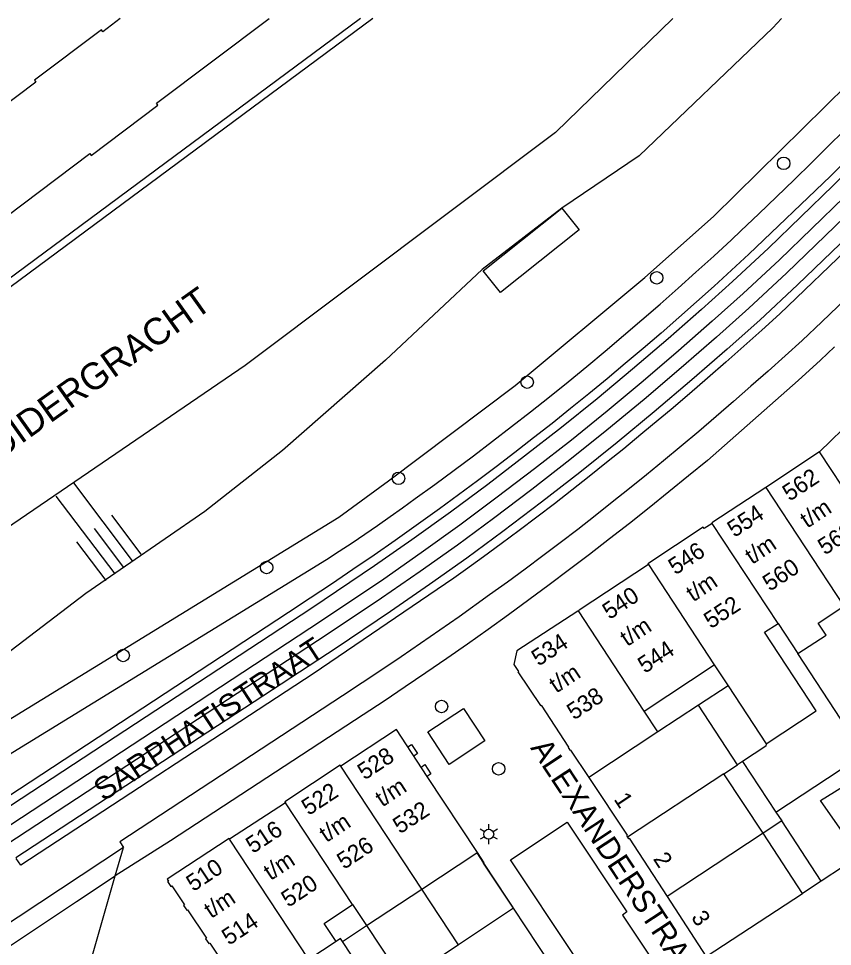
# Model space of a CAD drawing. Extents: x 122462 to 123306, y 485548 to 486417.
# Drawn here: x 123158.7 to 123231.7, y 486333.7 to 486417 of the extents above; entities that cross this region are included whole.
import ezdxf

# ---------------------------------------------------------------- set-up
doc = ezdxf.new("R2010")
doc.units = 0
for name, color, linetype in [('Level 1', 7, 'Continuous'), ('Level 16', 7, 'Continuous'), ('Level 17', 7, 'Continuous'), ('Level 19', 7, 'Continuous'), ('Level 20', 7, 'Continuous'), ('Level 22', 7, 'Continuous'), ('Level 24', 7, 'Continuous'), ('Level 37', 7, 'Continuous'), ('Level 4', 7, 'Continuous'), ('Level 40', 7, 'Continuous'), ('Level 48', 7, 'Continuous'), ('Level 50', 7, 'Continuous'), ('Level 53', 7, 'Continuous'), ('Level 57', 7, 'Continuous'), ('Level 58', 7, 'Continuous'), ('Level 59', 7, 'Continuous'), ('Level 60', 7, 'Continuous')]:
    doc.layers.add(name, color=color, linetype=linetype)

msp = doc.modelspace()

# ---------------------------------------------------------------- linework, layer by layer
at = {"layer": 'Level 1'}
for p, q in [((123235.039, 486382.526), (123230.529, 486378.09)), ((123230.529, 486378.09), (123225.704, 486374.909)), ((123226.804, 486362.716), (123228.584, 486360.007)), ((123214.811, 486354.86), (123221.09, 486358.986)), ((123221.09, 486358.986), (123222.318, 486357.117)), ((123222.318, 486357.117), (123225.737, 486351.915)), ((123219.662, 486355.372), (123216.038, 486352.992)), ((123223.171, 486350.032), (123219.662, 486355.372)), ((123216.038, 486352.992), (123214.811, 486354.86)), ((123221.95, 486349.23), (123223.171, 486350.032)), ((123199.84, 486342.17), (123195.333, 486349.001)), ((123225.459, 486343.89), (123221.95, 486349.23)), ((123182.621, 486346.637), (123177.614, 486343.359)), ((123228.995, 486338.508), (123225.459, 486343.89)), ((123194.85, 486338.882), (123199.786, 486342.135)), ((123199.786, 486342.135), (123199.84, 486342.17)), ((123232.673, 486340.925), (123230.678, 486339.614)), ((123230.678, 486339.614), (123228.995, 486338.508)), ((123189.886, 486335.611), (123194.85, 486338.882)), ((123188.645, 486337.494), (123189.886, 486335.611)), ((123191.074, 486329.173), (123187.728, 486334.188))]:
    msp.add_line(p, q, dxfattribs=at)
for points in [[(123167.795, 486416.958), (123166.225, 486415.776), (123166.105, 486415.936), (123160.112, 486411.424), (123160.232, 486411.265), (123148.252, 486402.244), (123148.132, 486402.404), (123143.918, 486399.231), (123148.989, 486392.497), (123153.203, 486395.67), (123153.083, 486395.83), (123165.062, 486404.849), (123165.182, 486404.69), (123171.175, 486409.202), (123171.055, 486409.362), (123181.145, 486416.958)], [(123225.704, 486374.909), (123220.88, 486371.729), (123220.909, 486371.686)], [(123220.909, 486371.686), (123220.173, 486371.225), (123220.09, 486371.35), (123215.12, 486368.069), (123215.176, 486367.987)], [(123215.176, 486367.987), (123208.959, 486363.9), (123208.9, 486363.855)], [(123208.9, 486363.855), (123208.84, 486363.809), (123203.38, 486360.249), (123203.1, 486359.029), (123203.528, 486358.392), (123203.479, 486358.36), (123205.499, 486355.35), (123205.551, 486355.384), (123208.021, 486351.614), (123207.969, 486351.579), (123208.15, 486351.309), (123208.198, 486351.342), (123209.819, 486348.906)], [(123228.584, 486360.007), (123231.114, 486361.67), (123230.403, 486362.751), (123232.701, 486364.262)], [(123225.737, 486351.915), (123230.237, 486354.872), (123225.602, 486361.926), (123226.804, 486362.716)], [(123195.333, 486349.001), (123192.57, 486353.189), (123187.585, 486349.906)], [(123187.585, 486349.906), (123187.529, 486349.989), (123182.559, 486346.729), (123182.621, 486346.637)], [(123240.501, 486343.552), (123243.294, 486339.302), (123238.114, 486336.108), (123230.623, 486346.845), (123236.113, 486350.23)], [(123209.819, 486348.906), (123213.265, 486343.727), (123213.209, 486343.689), (123213.305, 486343.55)], [(123177.614, 486343.359), (123177.559, 486343.439), (123172.019, 486339.769), (123172.126, 486339.611), (123172.049, 486339.559), (123172.342, 486339.12), (123172.426, 486339.176), (123173.557, 486337.472), (123173.473, 486337.416), (123173.758, 486336.987), (123173.842, 486337.043), (123175.539, 486334.486), (123175.455, 486334.43), (123175.739, 486333.999), (123175.821, 486334.054), (123179.246, 486328.91)], [(123213.305, 486343.55), (123213.4, 486343.41), (123213.457, 486343.447), (123216.848, 486338.233)], [(123216.848, 486338.233), (123220.33, 486332.88), (123220.37, 486332.839)], [(123187.163, 486334.191), (123186.094, 486335.813), (123188.645, 486337.494)], [(123187.728, 486334.188), (123187.553, 486334.451), (123187.163, 486334.191)]]:
    msp.add_lwpolyline(points, dxfattribs=at)
at = {"layer": 'Level 16'}
for points in [[(123190.452, 486416.958), (123152.084, 486388.57), (123141.474, 486380.8), (123112.044, 486361.399), (123104.38, 486356.401), (123085.904, 486344.353)], [(123217.361, 486416.958), (123206.829, 486406.748), (123179.003, 486385.844), (123152.655, 486367.889), (123137.927, 486357.79), (123128.826, 486350.852), (123125.877, 486348.714), (123125.807, 486348.517), (123125.744, 486347.678)]]:
    msp.add_lwpolyline(points, dxfattribs=at)
at = {"layer": 'Level 17'}
for p, q in [((123168.085, 486342.615), (123154.252, 486333.498)), ((123167.35, 486340.065), (123168.085, 486342.615)), ((123203.068, 486337.175), (123200.395, 486341.211)), ((123206.397, 486332.15), (123203.068, 486337.175))]:
    msp.add_line(p, q, dxfattribs=at)
for points in [[(123132.782, 486338.745), (123187.402, 486372.258), (123191.877, 486375.508), (123203.236, 486384.06), (123214.862, 486393.723), (123221.004, 486399.216), (123239.035, 486416.958)], [(123134.337, 486336.539), (123186.289, 486368.432), (123187.449, 486369.18), (123188.601, 486369.939), (123189.745, 486370.711), (123190.881, 486371.494), (123192.009, 486372.289), (123193.129, 486373.095), (123194.266, 486373.908), (123196.013, 486375.173), (123197.751, 486376.452), (123199.479, 486377.743), (123201.198, 486379.046), (123202.907, 486380.363), (123204.607, 486381.692), (123206.296, 486383.034), (123207.975, 486384.388), (123209.645, 486385.754), (123211.304, 486387.133), (123212.953, 486388.524), (123214.592, 486389.927), (123216.22, 486391.342), (123217.838, 486392.769), (123219.445, 486394.208), (123221.041, 486395.659), (123222.627, 486397.122), (123223.475, 486397.918), (123225.077, 486399.435), (123226.669, 486400.962), (123228.254, 486402.497), (123229.829, 486404.042), (123242.851, 486416.958)], [(123240.448, 486411.733), (123231.513, 486402.822), (123224.18, 486395.824), (123222.627, 486394.388), (123221.063, 486392.963), (123219.489, 486391.549), (123217.905, 486390.146), (123216.311, 486388.756), (123214.707, 486387.376), (123213.093, 486386.009), (123211.469, 486384.653), (123209.835, 486383.309), (123208.191, 486381.977), (123206.538, 486380.657), (123204.876, 486379.348), (123203.204, 486378.052), (123201.522, 486376.768), (123199.832, 486375.497), (123198.132, 486374.237), (123196.423, 486372.99), (123194.346, 486371.486), (123192.458, 486370.159), (123190.563, 486368.844), (123188.659, 486367.541), (123186.748, 486366.249), (123184.828, 486364.969), (123182.901, 486363.701), (123155.674, 486345.856)], [(123233.643, 486396.861), (123226.958, 486390.473), (123225.355, 486389.02), (123223.742, 486387.577), (123222.121, 486386.144), (123220.492, 486384.721), (123218.853, 486383.308), (123217.206, 486381.905), (123215.551, 486380.512), (123214.513, 486379.647), (123212.976, 486378.386), (123211.431, 486377.136), (123209.877, 486375.897), (123208.315, 486374.668), (123206.745, 486373.449), (123205.166, 486372.242), (123203.579, 486371.045), (123201.984, 486369.859), (123200.381, 486368.684), (123198.77, 486367.52), (123197.718, 486366.769), (123185.114, 486358.179), (123158.867, 486341.039), (123158.471, 486341.637)], [(123235.817, 486394.627), (123230.74, 486389.75), (123228.981, 486388.1), (123227.453, 486386.717), (123225.917, 486385.343), (123224.372, 486383.978), (123222.82, 486382.622), (123221.259, 486381.277), (123219.689, 486379.94), (123218.112, 486378.613), (123216.527, 486377.296), (123215.005, 486376.046), (123213.475, 486374.805), (123211.936, 486373.576), (123210.389, 486372.357), (123208.834, 486371.149), (123207.27, 486369.951), (123205.699, 486368.764), (123204.119, 486367.588), (123202.531, 486366.422), (123200.935, 486365.268), (123198.192, 486363.314), (123196.469, 486362.103), (123194.739, 486360.904), (123193, 486359.717), (123191.253, 486358.541), (123189.498, 486357.377), (123187.736, 486356.225), (123167.755, 486343.119), (123168.085, 486342.615)], [(123231.88, 486387.504), (123230.608, 486386.337), (123228.6, 486384.512), (123226.582, 486382.7), (123224.554, 486380.899), (123222.515, 486379.109), (123220.465, 486377.332), (123218.773, 486375.936), (123217.017, 486374.506), (123215.251, 486373.089), (123213.476, 486371.682), (123211.692, 486370.288), (123209.898, 486368.906), (123208.095, 486367.536), (123206.283, 486366.178), (123204.462, 486364.832), (123202.632, 486363.498), (123200.793, 486362.177), (123198.945, 486360.867), (123197.089, 486359.571), (123195.224, 486358.286), (123193.35, 486357.014), (123191.468, 486355.755), (123189.578, 486354.508), (123172.296, 486343.228), (123167.35, 486340.065)], [(123197.317, 486350.064), (123195.386, 486352.984), (123198.577, 486355.093), (123200.507, 486352.174), (123197.317, 486350.064)], [(123211.501, 486327.09), (123207.817, 486332.615), (123208.445, 486333.027), (123202.793, 486341.511), (123207.898, 486344.898), (123213.254, 486336.835), (123212.846, 486336.553), (123216.803, 486330.632), (123211.501, 486327.09)], [(123200.395, 486341.211), (123200.454, 486341.25), (123199.84, 486342.17)], [(123155.775, 486332.404), (123163.868, 486337.789), (123167.35, 486340.065)], [(123165.676, 486332.334), (123165.243, 486332.75), (123167.35, 486340.065)]]:
    msp.add_lwpolyline(points, dxfattribs=at)
at = {"layer": 'Level 19'}
for p, q in [((123189.359, 486416.958), (123151.706, 486389.073)), ((123233.016, 486353.261), (123228.584, 486360.007)), ((123222.318, 486357.117), (123219.662, 486355.372)), ((123223.633, 486350.335), (123223.171, 486350.032)), ((123223.633, 486350.335), (123226.616, 486345.796)), ((123226.616, 486345.796), (123234.512, 486350.984)), ((123226.616, 486345.796), (123227.142, 486344.996)), ((123227.142, 486344.996), (123225.459, 486343.89)), ((123230.678, 486339.614), (123227.142, 486344.996)), ((123198.141, 486333.888), (123194.85, 486338.882)), ((123203.068, 486337.175), (123198.141, 486333.888)), ((123187.728, 486334.188), (123189.886, 486335.611)), ((123189.886, 486335.611), (123193.225, 486330.608)), ((123198.141, 486333.888), (123194.336, 486331.35))]:
    msp.add_line(p, q, dxfattribs=at)
msp.add_lwpolyline([(123225.737, 486351.915), (123225.721, 486351.708), (123223.633, 486350.335)], dxfattribs=at)
at = {"layer": 'Level 20'}
msp.add_lwpolyline([(123227.128, 486416.958), (123226.347, 486416.118), (123214.358, 486404.642), (123207.4, 486399.966), (123200.277, 486394.449), (123191.597, 486386.324), (123182.341, 486378.222), (123175.379, 486372.758), (123164.712, 486365.388), (123158.016, 486360.276), (123153.237, 486354.953), (123145.688, 486350.946), (123140.068, 486347.272), (123131.328, 486340.807)], dxfattribs=at)
at = {"layer": 'Level 22'}
msp.add_line((123200.395, 486341.211), (123203.538, 486336.466), dxfattribs=at)
at = {"layer": 'Level 24'}
msp.add_line((123199.786, 486342.135), (123200.395, 486341.211), dxfattribs=at)
at = {"layer": 'Level 37'}
for points in [[(123241.03, 486411.185), (123231.744, 486401.974), (123225.952, 486396.381), (123222.721, 486393.366), (123219.946, 486390.881), (123216.94, 486388.248), (123213.765, 486385.527), (123210.569, 486382.869), (123207.368, 486380.288), (123204.076, 486377.707), (123200.759, 486375.175), (123197.416, 486372.695), (123193.966, 486370.217), (123190.616, 486367.88), (123184.983, 486364.082), (123156.102, 486345.165)], [(123242.034, 486410.153), (123232.751, 486400.945), (123226.939, 486395.332), (123223.692, 486392.302), (123220.904, 486389.806), (123217.883, 486387.161), (123214.693, 486384.426), (123211.482, 486381.755), (123208.265, 486379.161), (123204.957, 486376.568), (123201.624, 486374.024), (123198.265, 486371.533), (123194.8, 486369.043), (123191.437, 486366.696), (123185.777, 486362.88), (123156.905, 486343.969)], [(123242.948, 486409.215), (123233.663, 486400.005), (123227.574, 486394.133), (123224.193, 486390.984), (123221.287, 486388.391), (123218.124, 486385.639), (123214.783, 486382.796), (123211.462, 486380.052), (123208.135, 486377.388), (123204.717, 486374.728), (123201.271, 486372.12), (123198.042, 486369.744), (123194.714, 486367.37), (123191.238, 486364.965), (123186.373, 486361.706), (123157.637, 486342.879)], [(123243.952, 486408.183), (123234.67, 486398.976), (123228.56, 486393.083), (123225.163, 486389.918), (123222.242, 486387.313), (123219.064, 486384.548), (123215.707, 486381.691), (123212.37, 486378.935), (123209.028, 486376.258), (123205.594, 486373.586), (123202.132, 486370.966), (123198.888, 486368.578), (123195.543, 486366.192), (123192.054, 486363.778), (123187.166, 486360.503), (123158.44, 486341.683)]]:
    msp.add_lwpolyline(points, dxfattribs=at)
at = {"layer": 'Level 4'}
for p, q in [((123237.525, 486367.443), (123230.529, 486378.09)), ((123225.704, 486374.909), (123232.701, 486364.262)), ((123226.804, 486362.716), (123220.909, 486371.686)), ((123215.176, 486367.987), (123221.09, 486358.986)), ((123214.811, 486354.86), (123208.9, 486363.855)), ((123216.038, 486352.992), (123209.819, 486348.906)), ((123194.85, 486338.882), (123187.585, 486349.906)), ((123221.95, 486349.23), (123213.305, 486343.55)), ((123188.645, 486337.494), (123182.621, 486346.637)), ((123225.459, 486343.89), (123216.848, 486338.233)), ((123184.726, 486332.565), (123177.614, 486343.359)), ((123220.37, 486332.839), (123228.995, 486338.508)), ((123187.163, 486334.191), (123184.726, 486332.565))]:
    msp.add_line(p, q, dxfattribs=at)
at = {"layer": 'Level 40'}
for points in [[(123193.585, 486351.652), (123193.918, 486351.871), (123194.468, 486351.037), (123194.135, 486350.818)], [(123194.783, 486349.835), (123195.117, 486350.055), (123195.667, 486349.221), (123195.333, 486349.001)]]:
    msp.add_lwpolyline(points, dxfattribs=at)
at = {"layer": 'Level 48'}
msp.add_lwpolyline([(123201.906, 486392.386), (123200.346, 486394.343), (123207.4, 486399.966), (123208.96, 486398.009), (123201.906, 486392.386)], dxfattribs=at)
at = {"layer": 'Level 50'}
for p, q in [((123200.851, 486344.257), (123200.851, 486344.707)), ((123200.461, 486344.032), (123200.071, 486344.257)), ((123201.63, 486344.257), (123201.24, 486344.032)), ((123200.461, 486343.582), (123200.071, 486343.357)), ((123200.851, 486342.907), (123200.851, 486343.357)), ((123201.63, 486343.357), (123201.24, 486343.582))]:
    msp.add_line(p, q, dxfattribs=at)
msp.add_circle((123200.851, 486343.807), 0.45, dxfattribs=at)
at = {"layer": 'Level 53'}
for centre in [(123227.312, 486403.968), (123215.922, 486393.711), (123204.296, 486384.35), (123192.764, 486375.72), (123180.926, 486367.729), (123168.056, 486359.834), (123196.624, 486355.261), (123201.743, 486349.671)]:
    msp.add_circle(centre, 0.56, dxfattribs=at)
at = {"layer": 'Level 57'}
for p, q in [((123168.902, 486368.337), (123163.634, 486375.313)), ((123167.328, 486367.148), (123162.06, 486374.124)), ((123169.689, 486368.931), (123167.055, 486372.419)), ((123168.115, 486367.743), (123165.481, 486371.231)), ((123166.542, 486366.554), (123163.907, 486370.042))]:
    msp.add_line(p, q, dxfattribs=at)

# ---------------------------------------------------------------- texts
at = {"layer": 'Level 58'}
for s, rotation, p in [('562', 33.30586, (123227.835, 486373.625)), ('554', 33.30586, (123222.888, 486370.376)), ('t/m', 33.30586, (123229.42, 486371.21)), ('568', 33.30586, (123231.009, 486368.794)), ('t/m', 33.30586, (123224.473, 486367.961)), ('546', 33.43268, (123217.6, 486367.012)), ('560', 33.30586, (123226.061, 486365.545)), ('t/m', 33.43268, (123219.191, 486364.599)), ('540', 33.30586, (123211.683, 486363.013)), ('552', 33.43268, (123220.784, 486362.187)), ('t/m', 33.30586, (123213.269, 486360.599)), ('534', 33.30586, (123205.321, 486358.833)), ('544', 33.30586, (123214.857, 486358.183)), ('t/m', 33.30586, (123206.906, 486356.418)), ('538', 33.30586, (123208.495, 486354.002)), ('528', 33.31996, (123189.714, 486348.621)), ('522', 33.27308, (123184.697, 486345.441)), ('t/m', 33.31996, (123191.302, 486346.204)), ('1', 303.63297, (123212.029, 486346.942)), ('532', 33.31996, (123192.889, 486343.789)), ('t/m', 33.27308, (123186.282, 486343.025)), ('516', 33.31996, (123179.695, 486342.033)), ('526', 33.27308, (123187.869, 486340.609)), ('2', 303.06264, (123215.557, 486341.596)), ('510', 33.52513, (123174.354, 486338.618)), ('t/m', 33.31996, (123181.283, 486339.618)), ('520', 33.31996, (123182.871, 486337.204)), ('t/m', 33.52513, (123175.949, 486336.208)), ('514', 33.52513, (123177.545, 486333.799)), ('3', 303.07978, (123218.964, 486336.357))]:
    msp.add_text(s, height=1.5, rotation=rotation, dxfattribs=at).set_placement(p)
at = {"layer": 'Level 59'}
for s, rotation, p in [('SARPHATISTRAAT', 33.49778, (123166.28, 486346.712)), ('ALEXANDERSTRAAT', 303.37862, (123204.542, 486351.547))]:
    msp.add_text(s, height=2, rotation=rotation, dxfattribs=at).set_placement(p)
at = {"layer": 'Level 60'}
msp.add_text('PLANTAGE MUIDERGRACHT', height=2.4, rotation=35.45548, dxfattribs=at).set_placement((123140.153, 486365.414))

doc.saveas('drawing.dxf')
